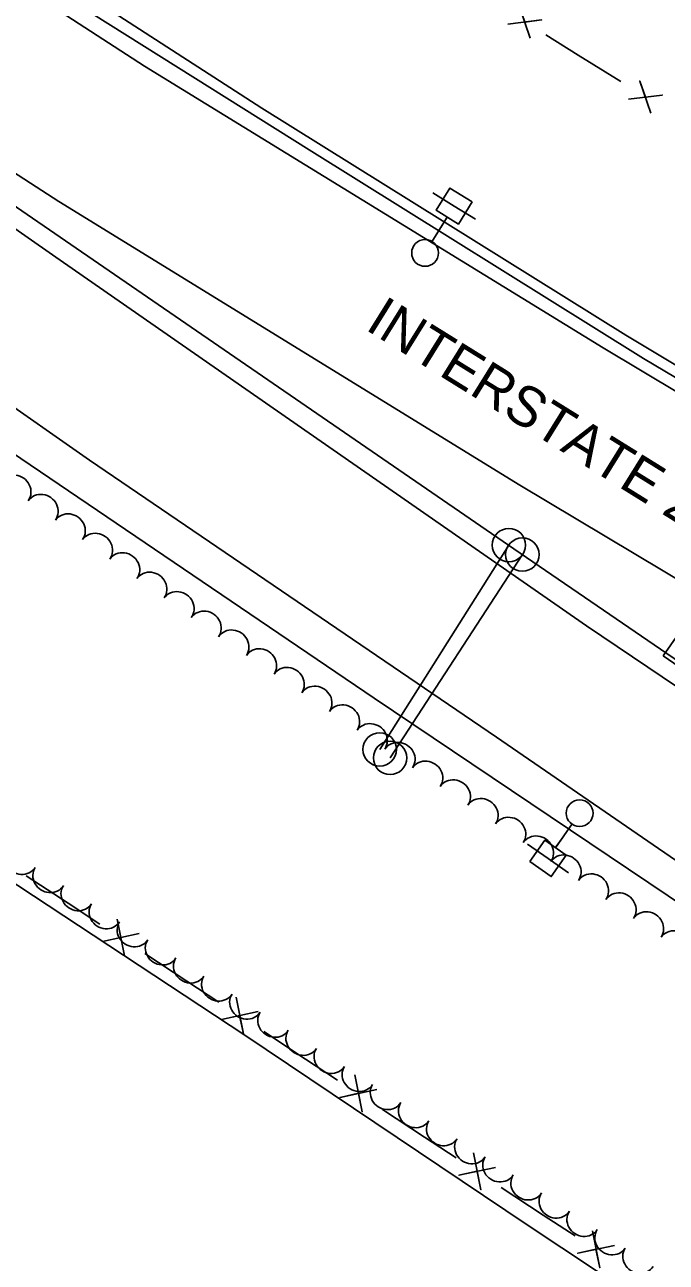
# Model space of a CAD drawing. Extents: x 1746010 to 1754829, y 655801 to 663091.
# Drawn here: x 1750940.1 to 1751132, y 659369.9 to 659740.2 of the extents above; entities that cross this region are included whole.
import ezdxf

# ---------------------------------------------------------------- set-up
doc = ezdxf.new("R2010")
doc.units = 0
for name, color, linetype in [('SURVEY - AERIAL SURVEY - Photo Control - Points - Elevations', 7, 'Continuous'), ('SURVEY - AERIAL SURVEY - Photo Control - Points - Locators', 7, 'Continuous'), ('SURVEY - AERIAL SURVEY - Photo Control - Points - Numbers', 7, 'Continuous'), ('SURVEY - AERIAL SURVEY - Photo Control with Text', 7, 'Continuous'), ('SURVEY - CENTERLINE - Existing Roads - Development', 7, 'Continuous'), ('SURVEY - CENTERLINE - Existing Roads Curve Text', 7, 'Continuous'), ('SURVEY - CENTERLINE - Existing Roads Text', 7, 'Continuous'), ('SURVEY - CENTERLINE - Preliminary - Development', 7, 'Continuous'), ('SURVEY - CONTROL - Points - Numbers', 7, 'Continuous')]:
    doc.layers.add(name, color=color, linetype=linetype)

msp = doc.modelspace()

# ---------------------------------------------------------------- linework, layer by layer
at = {"layer": 'SURVEY - AERIAL SURVEY - Photo Control - Points - Elevations'}
msp.add_lwpolyline([(1751901.75, 659229.66), (1751903.78, 659232.49), (1751820.15, 659271.12), (1751720.09, 659319), (1751608.79, 659375.48), (1751511.86, 659425.67), (1751414.79, 659477.82), (1751309.42, 659535.79), (1751238.02, 659576.37), (1751119.98, 659647.33), (1751011.07, 659715.27), (1750920.63, 659773.68), (1750818.05, 659842.07), (1750688.97, 659930.51), (1750687.2, 659926.86)], dxfattribs=at)
at = {"layer": 'SURVEY - AERIAL SURVEY - Photo Control - Points - Locators'}
for points in [[(1751850.89, 659069.97), (1751836.71, 659078.71), (1751698.09, 659167.45), (1751556.82, 659259.91), (1751409.51, 659356.6), (1751240.26, 659471.26), (1751108.21, 659560.28), (1750949.44, 659670.61), (1750790.01, 659782.16), (1750639.25, 659888.39), (1750537.27, 659960.87), (1750507.28, 659982.53)], [(1751692.52, 659270.52), (1751605.65, 659313.28), (1751476.09, 659381.66), (1751353.72, 659447.67), (1751225.98, 659520.03), (1751088.26, 659602.44), (1750950.33, 659687.25), (1750831.52, 659764.33), (1750532.19, 659979.6)], [(1751980.95, 659190.5), (1751865.03, 659241.97), (1751755.82, 659292.86), (1751627.46, 659356.04), (1751498.69, 659424), (1751376.94, 659489.68), (1751250.14, 659561.52), (1751113.15, 659643.48), (1750975.97, 659727.83), (1750858.05, 659804.33), (1750722.4, 659896.24), (1750620.83, 659969.19)], [(1751811.46, 659040.6), (1751803.54, 659045.66), (1751651.7, 659139.14), (1751560.97, 659192.86), (1751430.95, 659277.83), (1751226.31, 659416.5), (1751044.68, 659538.71), (1750870.37, 659656.91), (1750693.9, 659781.14), (1750567.77, 659872.76), (1750445.81, 659959.59)], [(1750464.75, 659959.09), (1750533.91, 659909.95), (1750645.13, 659831.38), (1750753.4, 659754.5), (1750870.59, 659672.13), (1750959.5, 659609.93), (1751081.2, 659527.03), (1751199.52, 659445.74), (1751320.31, 659364.23), (1751443.12, 659281.31), (1751559.93, 659204.83), (1751660.4, 659140.92), (1751744.29, 659087.1), (1751814.04, 659042.53)], [(1751981.66, 659195.26), (1751889.68, 659234.85), (1751784.21, 659284.64), (1751694.2, 659328.1), (1751603.81, 659373.71), (1751512.94, 659420.78), (1751440.06, 659459.77), (1751340.52, 659515.91), (1751224.32, 659581.45), (1751125.19, 659640.31), (1751025.2, 659702.76), (1750930.86, 659762.02), (1750841.47, 659821.93), (1750746.73, 659885.97), (1750687.69, 659926.53)], [(1750442.38, 659808.99), (1750465.21, 659794.81), (1750538.04, 659744.98), (1750643.02, 659676.78), (1750718.06, 659626.91), (1750787.91, 659581.42), (1750854.73, 659538.04), (1750906.32, 659503.45), (1751005.99, 659437.83), (1751090.42, 659381.01), (1751173.7, 659325.75), (1751180.54, 659321.31)]]:
    msp.add_lwpolyline(points, dxfattribs=at)
at = {"layer": 'SURVEY - AERIAL SURVEY - Photo Control - Points - Numbers'}
msp.add_lwpolyline([(1751210.77, 659498.28), (1751086.47, 659583.36), (1750914.66, 659701.33), (1750734.42, 659828.18), (1750551.67, 659956.79), (1750517.76, 659981.3)], dxfattribs=at)
at = {"layer": 'SURVEY - AERIAL SURVEY - Photo Control with Text'}
for p, q in [((1751046.31, 659523.33), (1751084.95, 659584.46)), ((1751084.96, 659584.42), (1751084.96, 659584.42)), ((1751088.98, 659581.64), (1751049.41, 659520.79)), ((1751088.99, 659581.6), (1751088.99, 659581.6)), ((1751046.32, 659523.29), (1751046.32, 659523.29)), ((1751049.42, 659520.75), (1751049.42, 659520.75))]:
    msp.add_line(p, q, dxfattribs=at)
for centre in [(1751084.95, 659584.46), (1751088.98, 659581.64), (1751046.31, 659523.33), (1751049.41, 659520.79)]:
    msp.add_circle(centre, 5, dxfattribs=at)
at = {"layer": 'SURVEY - CENTERLINE - Existing Roads - Development'}
for points in [[(1751084.61, 659740.37), (1751094.73, 659741.64), (1751089.72, 659740.98), (1751088.03, 659745.82), (1751091.32, 659736.19)], [(1751096.04, 659737.13), (1751105.71, 659731.1)], [(1751105.71, 659731.1), (1751118.44, 659723.16)], [(1751120.68, 659717.88), (1751130.8, 659719.15), (1751125.78, 659718.49), (1751124.09, 659723.33), (1751127.38, 659713.7)], [(1750953.09, 659477.3), (1750940.55, 659485.53)], [(1750962.62, 659471.04), (1750953.09, 659477.3)], [(1750974.4, 659468.21), (1750963.41, 659465.86), (1750968.86, 659467.07), (1750970.01, 659461.53), (1750967.8, 659472.55)], [(1750988.62, 659453.97), (1750976.08, 659462.21)], [(1750998.15, 659447.72), (1750988.62, 659453.97)], [(1751009.93, 659444.89), (1750998.94, 659442.54), (1751004.39, 659443.74), (1751005.54, 659438.2), (1751003.33, 659449.22)], [(1751024.15, 659430.65), (1751011.61, 659438.88)], [(1751033.68, 659424.39), (1751024.15, 659430.65)], [(1751045.46, 659421.56), (1751034.47, 659419.21), (1751039.92, 659420.42), (1751041.07, 659414.88), (1751038.86, 659425.9)], [(1751059.68, 659407.33), (1751047.14, 659415.56)], [(1751069.21, 659401.07), (1751059.68, 659407.33)], [(1751080.99, 659398.24), (1751070, 659395.89), (1751075.45, 659397.09), (1751076.6, 659391.55), (1751074.39, 659402.58)], [(1751095.21, 659384), (1751082.67, 659392.23)], [(1751104.74, 659377.75), (1751095.21, 659384)], [(1751116.52, 659374.92), (1751105.53, 659372.57), (1751110.98, 659373.77), (1751112.13, 659368.23), (1751109.92, 659379.25)]]:
    msp.add_lwpolyline(points, dxfattribs=at)
at = {"layer": 'SURVEY - CENTERLINE - Existing Roads Curve Text'}
for p, q in [((1751068.57, 659685.93), (1751062.2, 659689.88)), ((1751068.57, 659685.93), (1751074.94, 659681.97)), ((1751061.93, 659675.22), (1751066.52, 659682.61)), ((1751066.3, 659682.27), (1751064.62, 659679.55)), ((1751103.87, 659501.04), (1751098.88, 659493.92)), ((1751096.65, 659490.72), (1751090.5, 659495.02)), ((1751099.11, 659494.24), (1751100.95, 659496.86)), ((1751096.65, 659490.72), (1751102.79, 659486.42))]:
    msp.add_line(p, q, dxfattribs=at)
for points in [[(1751073.94, 659687.18), (1751069.83, 659680.55), (1751063.2, 659684.67), (1751067.31, 659691.3)], [(1751091.21, 659489.76), (1751095.69, 659496.15), (1751102.08, 659491.68), (1751097.61, 659485.29)]]:
    msp.add_lwpolyline(points, close=True, dxfattribs=at)
for centre in [(1751059.87, 659671.9), (1751106.11, 659504.24)]:
    msp.add_circle(centre, 4, dxfattribs=at)
at = {"layer": 'SURVEY - CENTERLINE - Existing Roads Text'}
for centre, major_axis in [((1750937.1, 659600.66), (4.07, -2.91)), ((1750945.23, 659594.84), (4.07, -2.91)), ((1750953.36, 659589.02), (4.07, -2.91)), ((1750961.5, 659583.2), (4.07, -2.91)), ((1750969.63, 659577.38), (4.07, -2.91)), ((1750977.76, 659571.56), (4.07, -2.91)), ((1750985.89, 659565.73), (4.07, -2.91)), ((1750994.02, 659559.91), (4.07, -2.91)), ((1751002.28, 659554.28), (4.14, -2.8)), ((1751010.57, 659548.67), (4.14, -2.8)), ((1751018.85, 659543.07), (4.14, -2.8)), ((1751027.13, 659537.46), (4.14, -2.8)), ((1751035.41, 659531.86), (4.14, -2.8)), ((1751043.69, 659526.25), (4.14, -2.8)), ((1751051.98, 659520.65), (4.14, -2.8)), ((1751060.26, 659515.04), (4.14, -2.8)), ((1751068.54, 659509.44), (4.14, -2.8)), ((1751076.82, 659503.84), (4.14, -2.8)), ((1751085.11, 659498.23), (4.14, -2.8)), ((1751093.39, 659492.62), (4.12, -2.84)), ((1750939.09, 659490.71), (-4.2, 2.72)), ((1751101.63, 659486.95), (4.12, -2.84)), ((1750947.49, 659485.27), (-4.2, 2.72)), ((1751109.86, 659481.28), (4.12, -2.84)), ((1750955.89, 659479.85), (-4.21, 2.71)), ((1751118.1, 659475.61), (4.12, -2.84)), ((1750964.3, 659474.44), (-4.21, 2.71)), ((1751126.34, 659469.94), (4.12, -2.84)), ((1750972.71, 659469.03), (-4.21, 2.71)), ((1751134.58, 659464.27), (4.12, -2.84)), ((1750981.12, 659463.62), (-4.21, 2.71)), ((1750989.53, 659458.21), (-4.21, 2.71)), ((1750997.94, 659452.8), (-4.21, 2.71)), ((1751006.35, 659447.39), (-4.21, 2.71)), ((1751014.76, 659441.98), (-4.21, 2.71)), ((1751023.17, 659436.57), (-4.21, 2.71)), ((1751031.58, 659431.16), (-4.21, 2.71)), ((1751039.99, 659425.74), (-4.21, 2.71)), ((1751048.4, 659420.33), (-4.21, 2.71)), ((1751056.81, 659414.92), (-4.21, 2.71)), ((1751065.23, 659409.51), (-4.21, 2.71)), ((1751073.64, 659404.1), (-4.21, 2.71)), ((1751082.05, 659398.69), (-4.21, 2.71)), ((1751090.46, 659393.28), (-4.21, 2.71)), ((1751098.87, 659387.87), (-4.18, 2.75)), ((1751107.22, 659382.37), (-4.18, 2.75)), ((1751115.57, 659376.87), (-4.18, 2.75)), ((1751123.92, 659371.37), (-4.18, 2.75))]:
    msp.add_ellipse(centre, major_axis=major_axis, ratio=0.940188, start_param=0, end_param=3.141593, dxfattribs=at)
at = {"layer": 'SURVEY - CENTERLINE - Preliminary - Development'}
msp.add_lwpolyline([(1751131.13, 659551.36), (1751135.72, 659557.92), (1751143.91, 659552.18), (1751139.33, 659545.63), (1751131.13, 659551.36)], dxfattribs=at)

# ---------------------------------------------------------------- texts
at = {"layer": 'SURVEY - CONTROL - Points - Numbers'}
msp.add_text('INTERSTATE 24/40', height=12, rotation=328.1505, dxfattribs=at).set_placement((1751041.66, 659649.16))

doc.saveas('drawing.dxf')
